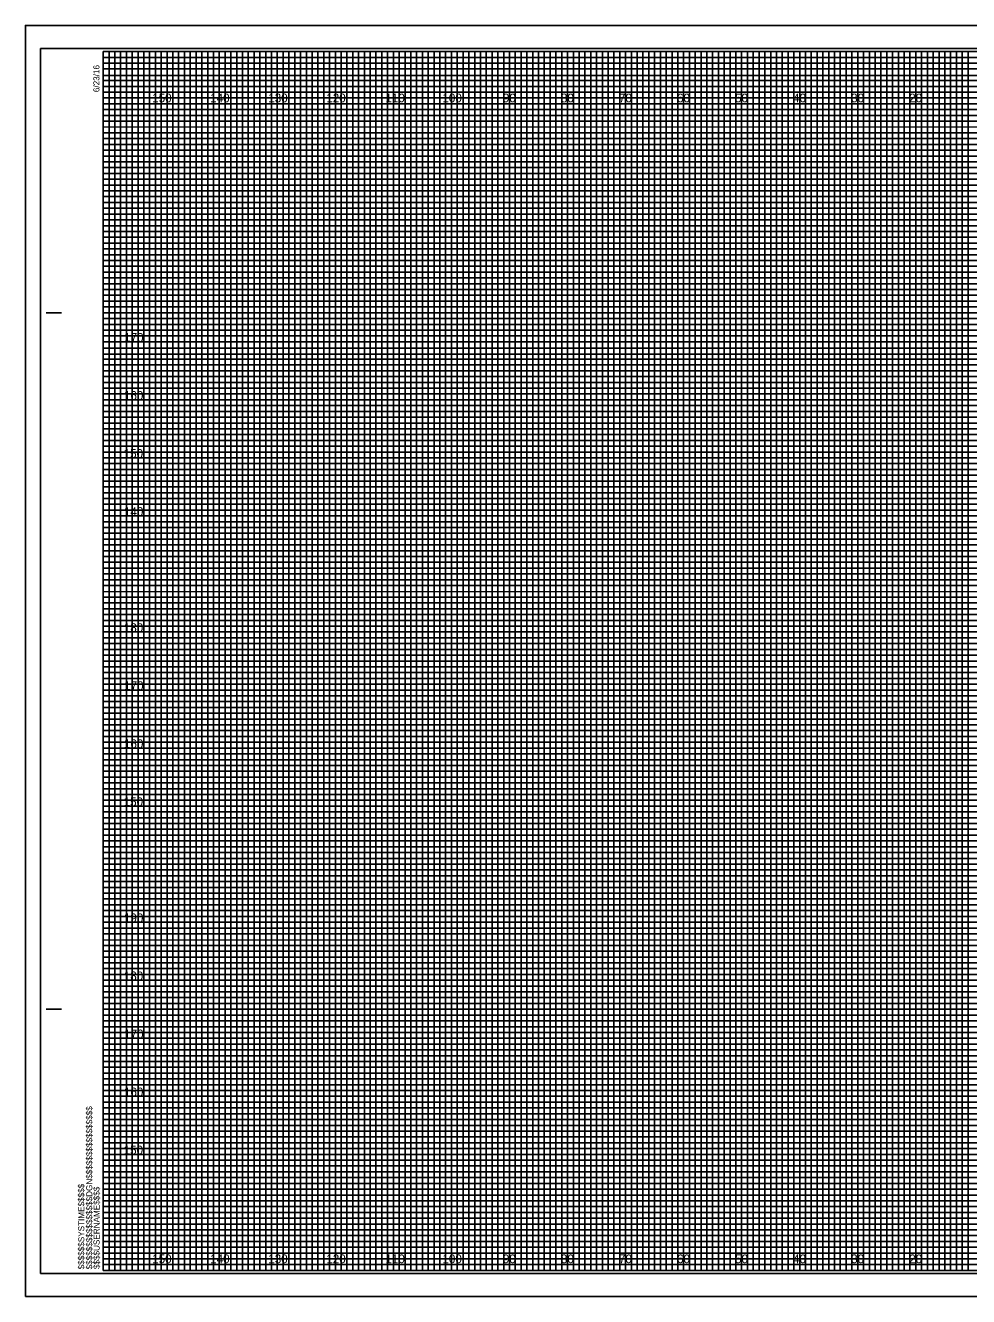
# Model space of a CAD drawing. Extents: x -13 to 323, y -5 to 4834.
# Drawn here: x -13.4 to 149.1, y 1095.5 to 1314.5 of the extents above; entities that cross this region are included whole.
import ezdxf

# ---------------------------------------------------------------- set-up
doc = ezdxf.new("R2010")
doc.units = 0
for name, color, linetype in [('Exist Cross Section Cell', 7, 'Continuous'), ('Exist XS Center Line Elevation Label', 7, 'Continuous'), ('Exist XS Ground Line', 7, 'Continuous'), ('Prop CMT Pvmt Course 1', 7, 'Continuous'), ('Prop CMT Pvmt Course 2', 7, 'Continuous'), ('Prop CMT Pvmt Course 3', 7, 'Continuous'), ('Prop CMT Pvmt Surface Shoulder', 7, 'Continuous'), ('Prop CMT Shld Paved Course 1', 7, 'Continuous'), ('Prop CMT Shld Paved Course 2', 7, 'Continuous'), ('Prop CMT Shld Paved Course 3', 7, 'Continuous'), ('Prop CMT Slope Grass', 7, 'Continuous')]:
    doc.layers.add(name, color=color, linetype=linetype)

msp = doc.modelspace()

# ---------------------------------------------------------------- linework, layer by layer
at = {"layer": 'Exist XS Center Line Elevation Label'}
for points in [[(0, 1310), (5, 1310), (5, 1100), (15, 1100), (15, 1310), (25, 1310), (25, 1100), (35, 1100), (35, 1310), (45, 1310), (45, 1100), (55, 1100), (55, 1310), (65, 1310), (65, 1100), (75, 1100), (75, 1310), (85, 1310), (85, 1100), (95, 1100), (95, 1310), (105, 1310), (105, 1100), (115, 1100), (115, 1310), (125, 1310), (125, 1100), (135, 1100), (135, 1310), (145, 1310), (145, 1100), (155, 1100)], [(0, 1305), (275, 1305)], [(0, 1285), (320, 1285), (320, 1295), (0, 1295)], [(0, 1265), (320, 1265), (320, 1275), (0, 1275)], [(0, 1245), (320, 1245), (320, 1255), (0, 1255)], [(0, 1225), (320, 1225), (320, 1235), (0, 1235)], [(0, 1205), (320, 1205), (320, 1215), (0, 1215)], [(0, 1185), (320, 1185), (320, 1195), (0, 1195)], [(0, 1165), (320, 1165), (320, 1175), (0, 1175)], [(0, 1145), (320, 1145), (320, 1155), (0, 1155)], [(0, 1125), (320, 1125), (320, 1135), (0, 1135)], [(0, 1105), (320, 1105), (320, 1115), (0, 1115)]]:
    msp.add_lwpolyline(points, dxfattribs=at)
at = {"layer": 'Exist XS Ground Line'}
for p, q in [((10, 1310), (0, 1310)), ((10, 1100), (10, 1310)), ((30, 1310), (20, 1310)), ((20, 1310), (20, 1100)), ((30, 1100), (30, 1310)), ((50, 1310), (40, 1310)), ((40, 1310), (40, 1100)), ((50, 1100), (50, 1310)), ((70, 1310), (60, 1310)), ((60, 1310), (60, 1100)), ((70, 1100), (70, 1310)), ((90, 1310), (80, 1310)), ((80, 1310), (80, 1100)), ((90, 1100), (90, 1310)), ((110, 1310), (100, 1310)), ((100, 1310), (100, 1100)), ((110, 1100), (110, 1310)), ((130, 1310), (120, 1310)), ((120, 1310), (120, 1100)), ((130, 1100), (130, 1310)), ((150, 1310), (140, 1310)), ((140, 1310), (140, 1100)), ((20, 1100), (10, 1100)), ((40, 1100), (30, 1100)), ((60, 1100), (50, 1100)), ((80, 1100), (70, 1100)), ((100, 1100), (90, 1100)), ((120, 1100), (110, 1100)), ((140, 1100), (130, 1100))]:
    msp.add_line(p, q, dxfattribs=at)
for points in [[(0, 1300), (320, 1300), (320, 1290), (0, 1290)], [(0, 1280), (320, 1280), (320, 1270), (0, 1270)], [(0, 1260), (320, 1260), (320, 1250), (0, 1250)], [(0, 1240), (320, 1240), (320, 1230), (0, 1230)], [(0, 1220), (320, 1220), (320, 1210), (0, 1210)], [(0, 1200), (320, 1200), (320, 1190), (0, 1190)], [(0, 1180), (320, 1180), (320, 1170), (0, 1170)], [(0, 1160), (320, 1160), (320, 1150), (0, 1150)], [(0, 1140), (320, 1140), (320, 1130), (0, 1130)], [(0, 1120), (320, 1120), (320, 1110), (0, 1110)]]:
    msp.add_lwpolyline(points, dxfattribs=at)
at = {"layer": 'Prop CMT Pvmt Course 1'}
for points in [[(0, 1100), (1, 1100), (1, 1310), (2, 1310), (2, 1100)], [(2, 1100), (3, 1100), (3, 1310), (4, 1310), (4, 1100)], [(5, 1100), (6, 1100), (6, 1310), (7, 1310), (7, 1100)], [(7, 1100), (8, 1100), (8, 1310), (9, 1310), (9, 1100)], [(10, 1100), (11, 1100), (11, 1310), (12, 1310), (12, 1100)], [(12, 1100), (13, 1100), (13, 1310), (14, 1310), (14, 1100)], [(15, 1100), (16, 1100), (16, 1310), (17, 1310), (17, 1100)], [(17, 1100), (18, 1100), (18, 1310), (19, 1310), (19, 1100)], [(20, 1100), (21, 1100), (21, 1310), (22, 1310), (22, 1100)], [(22, 1100), (23, 1100), (23, 1310), (24, 1310), (24, 1100)], [(25, 1100), (26, 1100), (26, 1310), (27, 1310), (27, 1100)], [(27, 1100), (28, 1100), (28, 1310), (29, 1310), (29, 1100)], [(30, 1100), (31, 1100), (31, 1310), (32, 1310), (32, 1100)], [(32, 1100), (33, 1100), (33, 1310), (34, 1310), (34, 1100)], [(35, 1100), (36, 1100), (36, 1310), (37, 1310), (37, 1100)], [(37, 1100), (38, 1100), (38, 1310), (39, 1310), (39, 1100)], [(40, 1100), (41, 1100), (41, 1310), (42, 1310), (42, 1100)], [(42, 1100), (43, 1100), (43, 1310), (44, 1310), (44, 1100)], [(45, 1100), (46, 1100), (46, 1310), (47, 1310), (47, 1100)], [(47, 1100), (48, 1100), (48, 1310), (49, 1310), (49, 1100)], [(50, 1100), (51, 1100), (51, 1310), (52, 1310), (52, 1100)], [(52, 1100), (53, 1100), (53, 1310), (54, 1310), (54, 1100)], [(55, 1100), (56, 1100), (56, 1310), (57, 1310), (57, 1100)], [(57, 1100), (58, 1100), (58, 1310), (59, 1310), (59, 1100)], [(60, 1100), (61, 1100), (61, 1310), (62, 1310), (62, 1100)], [(62, 1100), (63, 1100), (63, 1310), (64, 1310), (64, 1100)], [(65, 1100), (66, 1100), (66, 1310), (67, 1310), (67, 1100)], [(67, 1100), (68, 1100), (68, 1310), (69, 1310), (69, 1100)], [(70, 1100), (71, 1100), (71, 1310), (72, 1310), (72, 1100)], [(72, 1100), (73, 1100), (73, 1310), (74, 1310), (74, 1100)], [(75, 1100), (76, 1100), (76, 1310), (77, 1310), (77, 1100)], [(77, 1100), (78, 1100), (78, 1310), (79, 1310), (79, 1100)], [(80, 1100), (81, 1100), (81, 1310), (82, 1310), (82, 1100)], [(82, 1100), (83, 1100), (83, 1310), (84, 1310), (84, 1100)], [(85, 1100), (86, 1100), (86, 1310), (87, 1310), (87, 1100)], [(87, 1100), (88, 1100), (88, 1310), (89, 1310), (89, 1100)], [(90, 1100), (91, 1100), (91, 1310), (92, 1310), (92, 1100)], [(92, 1100), (93, 1100), (93, 1310), (94, 1310), (94, 1100)], [(95, 1100), (96, 1100), (96, 1310), (97, 1310), (97, 1100)], [(97, 1100), (98, 1100), (98, 1310), (99, 1310), (99, 1100)], [(100, 1100), (101, 1100), (101, 1310), (102, 1310), (102, 1100)], [(102, 1100), (103, 1100), (103, 1310), (104, 1310), (104, 1100)], [(105, 1100), (106, 1100), (106, 1310), (107, 1310), (107, 1100)], [(107, 1100), (108, 1100), (108, 1310), (109, 1310), (109, 1100)], [(110, 1100), (111, 1100), (111, 1310), (112, 1310), (112, 1100)], [(112, 1100), (113, 1100), (113, 1310), (114, 1310), (114, 1100)], [(115, 1100), (116, 1100), (116, 1310), (117, 1310), (117, 1100)], [(117, 1100), (118, 1100), (118, 1310), (119, 1310), (119, 1100)], [(120, 1100), (121, 1100), (121, 1310), (122, 1310), (122, 1100)], [(122, 1100), (123, 1100), (123, 1310), (124, 1310), (124, 1100)], [(125, 1100), (126, 1100), (126, 1310), (127, 1310), (127, 1100)], [(127, 1100), (128, 1100), (128, 1310), (129, 1310), (129, 1100)], [(130, 1100), (131, 1100), (131, 1310), (132, 1310), (132, 1100)], [(132, 1100), (133, 1100), (133, 1310), (134, 1310), (134, 1100)], [(135, 1100), (136, 1100), (136, 1310), (137, 1310), (137, 1100)], [(137, 1100), (138, 1100), (138, 1310), (139, 1310), (139, 1100)], [(140, 1100), (141, 1100), (141, 1310), (142, 1310), (142, 1100)], [(142, 1100), (143, 1100), (143, 1310), (144, 1310), (144, 1100)], [(145, 1100), (146, 1100), (146, 1310), (147, 1310), (147, 1100)], [(147, 1100), (148, 1100), (148, 1310), (149, 1310), (149, 1100)]]:
    msp.add_lwpolyline(points, dxfattribs=at)
at = {"layer": 'Prop CMT Pvmt Course 2'}
for p, q in [((323.3, 1314.5), (-13.4, 1314.5)), ((-13.4, 1314.5), (-13.4, 1095.5)), ((-13.4, 1095.5), (323.3, 1095.5))]:
    msp.add_line(p, q, dxfattribs=at)
at = {"layer": 'Prop CMT Pvmt Surface Shoulder'}
for p, q in [((-9.8, 1265), (-7.3, 1265)), ((-9.7, 1265), (-7.2, 1265)), ((-9.8, 1145), (-7.3, 1145)), ((-9.7, 1145), (-7.2, 1145)), ((0, 1100), (0, 1100)), ((0, 1100), (0, 1100)), ((0, 1100), (0, 1100)), ((0, 1100), (0, 1100)), ((0, 1100), (0, 1100)), ((0, 1100), (0, 1100)), ((0, 1100), (0, 1100))]:
    msp.add_line(p, q, dxfattribs=at)
msp.add_lwpolyline([(320, 1310), (0, 1310), (0, 1100), (320, 1100)], close=True, dxfattribs=at)
at = {"layer": 'Prop CMT Shld Paved Course 1'}
msp.add_lwpolyline([(-13.4, 1095.5), (323.3, 1095.5), (323.3, 1314.5), (-13.4, 1314.5)], close=True, dxfattribs=at)
at = {"layer": 'Prop CMT Shld Paved Course 2'}
msp.add_lwpolyline([(-10.8, 1099.5), (322.4, 1099.5), (322.4, 1310.5), (-10.8, 1310.5)], close=True, dxfattribs=at)
at = {"layer": 'Prop CMT Shld Paved Course 3'}
for p, q in [((10, 1100), (10, 1310)), ((20, 1100), (20, 1310)), ((30, 1100), (30, 1310)), ((40, 1100), (40, 1310)), ((50, 1100), (50, 1310)), ((60, 1100), (60, 1310)), ((70, 1100), (70, 1310)), ((80, 1100), (80, 1310)), ((90, 1100), (90, 1310)), ((100, 1100), (100, 1310)), ((110, 1100), (110, 1310)), ((120, 1100), (120, 1310)), ((130, 1100), (130, 1310)), ((140, 1100), (140, 1310)), ((0, 1300), (320, 1300)), ((0, 1290), (320, 1290)), ((0, 1280), (320, 1280)), ((0, 1270), (320, 1270)), ((0, 1260), (320, 1260)), ((0, 1250), (320, 1250)), ((0, 1240), (320, 1240)), ((0, 1230), (320, 1230)), ((0, 1220), (320, 1220)), ((0, 1210), (320, 1210)), ((0, 1200), (320, 1200)), ((0, 1190), (320, 1190)), ((0, 1180), (320, 1180)), ((0, 1170), (320, 1170)), ((0, 1160), (320, 1160)), ((0, 1150), (320, 1150)), ((0, 1140), (320, 1140)), ((0, 1130), (320, 1130)), ((0, 1120), (320, 1120)), ((0, 1110), (320, 1110))]:
    msp.add_line(p, q, dxfattribs=at)
at = {"layer": 'Prop CMT Slope Grass'}
for p, q in [((0, 1309), (260, 1309)), ((260, 1307.98), (0, 1307.98)), ((0, 1307.98), (0, 1307)), ((0, 1307), (260, 1307)), ((260, 1305.89), (0, 1305.89)), ((0, 1305.89), (0, 1304)), ((0, 1304), (320, 1304))]:
    msp.add_line(p, q, dxfattribs=at)
for points in [[(0, 1303), (270, 1303), (320, 1303), (320, 1302), (0, 1302)], [(0, 1301), (320, 1301), (320, 1299), (0, 1299)], [(0, 1298), (320, 1298), (320, 1297), (0, 1296.98)], [(0, 1296), (320, 1296), (320, 1294), (0, 1294)], [(0, 1293), (320, 1293), (320, 1292), (0, 1292)], [(0, 1291), (320, 1291), (320, 1289), (0, 1289)], [(0, 1288), (320, 1288), (320, 1287), (0, 1287)], [(0, 1286), (320, 1286), (320, 1284), (0, 1284)], [(0, 1283), (320, 1283), (320, 1282), (0, 1282)], [(0, 1281), (320, 1281), (320, 1279), (0, 1279)], [(0, 1278), (320, 1278), (320, 1277), (0, 1277)], [(0, 1276), (320, 1276), (320, 1273.95), (320, 1273), (320, 1272), (0, 1272)], [(0, 1274), (320, 1274), (320, 1273), (0, 1273)], [(0, 1271), (320, 1271), (320, 1269), (0, 1269.03)], [(0, 1269.03), (320, 1269), (320, 1268), (0, 1268)], [(0, 1267), (320, 1267), (320, 1266), (0, 1266)], [(0, 1264), (320, 1264), (320, 1263), (0, 1263)], [(0, 1262), (320, 1262), (320, 1261), (0, 1261)], [(-0.07, 1258.89), (320, 1258.89), (320, 1257.88), (-0.07, 1257.88)], [(0, 1257), (320, 1257), (320, 1256), (0, 1256)], [(0, 1254), (320, 1254), (320, 1253), (0, 1253)], [(0, 1252), (320, 1252), (320, 1251), (0, 1251)], [(0, 1249), (320, 1249), (320, 1248), (0, 1248)], [(0, 1247), (320, 1247), (320, 1246), (0, 1246)], [(0, 1244), (320, 1244), (320, 1243), (0, 1243)], [(0, 1242), (320, 1242), (320, 1241), (0, 1241)], [(0, 1239), (320, 1239), (319.99, 1237.98), (0, 1238)], [(0, 1237), (320, 1237), (320, 1236), (0, 1236)], [(0, 1234), (320, 1234), (320, 1233), (0, 1233)], [(0, 1232), (320, 1232), (320, 1231), (0, 1231)], [(0, 1229), (320, 1229), (320, 1228), (0, 1228)], [(0, 1227), (320, 1227), (320, 1226), (0, 1226)], [(0, 1224), (320, 1224), (320, 1223), (0, 1223)], [(0, 1222), (320, 1222), (320, 1221), (0, 1221)], [(0, 1219), (320, 1219), (320, 1218), (0, 1218)], [(0, 1216.99), (320.07, 1216.91), (320, 1216), (0, 1216)], [(0, 1214), (320, 1214), (320, 1213), (0, 1213)], [(0, 1212), (320, 1212), (320, 1211), (0, 1211)], [(0, 1209), (320, 1209), (320, 1208), (0, 1208)], [(0, 1207), (320, 1207), (320, 1206), (0, 1206)], [(0, 1204), (320, 1204), (320, 1203), (0, 1203)], [(0, 1202), (320, 1202), (320, 1201), (0, 1201)], [(0, 1199), (320, 1199), (320, 1198), (0, 1198)], [(0, 1197), (320, 1197), (320, 1196), (0, 1196)], [(0, 1194), (320, 1194), (320, 1193), (0, 1193)], [(0, 1192), (320, 1192), (320, 1191), (0, 1191)], [(0, 1189), (320, 1189), (320, 1188), (0, 1188)], [(0, 1187), (320, 1187), (320, 1186), (0, 1186)], [(0, 1184), (320, 1184), (320, 1183), (0, 1183)], [(0, 1182), (320, 1182), (320, 1181), (0, 1181)], [(0, 1179), (320, 1179), (319.99, 1177.98), (0, 1178)], [(0, 1177), (320, 1177), (320, 1176), (0, 1176)], [(0, 1174), (320, 1174), (320, 1173), (0, 1173)], [(0, 1172), (320, 1172), (320, 1171), (0, 1171)], [(0, 1169), (320, 1169), (320, 1168), (0, 1168)], [(0, 1167), (320, 1167), (320, 1166), (0, 1166)], [(0, 1164), (320, 1164), (320, 1163), (0, 1163)], [(0, 1162), (320, 1162), (320, 1161), (0, 1161)], [(0, 1159), (320, 1159), (320, 1158), (0, 1158)], [(0, 1156.99), (320.07, 1156.91), (320, 1156), (0, 1156)], [(0, 1154), (320, 1154), (320, 1153), (0, 1153)], [(0, 1152), (320, 1152), (320, 1151), (0, 1151)], [(0, 1149), (320, 1149), (320, 1148), (0, 1148)], [(0, 1147), (320, 1147), (320, 1146), (0, 1146)], [(0, 1144), (320, 1144), (320, 1143), (0, 1143)], [(0, 1142), (320, 1142), (320, 1141), (0, 1141)], [(0, 1139), (320, 1139), (320, 1138), (0, 1138)], [(0, 1137), (320, 1137), (320, 1136), (0, 1136)], [(0, 1134), (320, 1134), (320, 1133), (0, 1133)], [(0, 1132), (320, 1132), (320, 1131), (0, 1131)], [(0, 1129), (320, 1129), (320, 1128), (0, 1128)], [(0, 1127), (320, 1127), (320, 1126), (0, 1126)], [(0, 1124), (320, 1124), (320, 1123), (0, 1123)], [(0, 1122), (320, 1122), (320, 1121), (0, 1121)], [(0, 1119), (320, 1119), (320, 1118), (0, 1118)], [(0, 1117), (320, 1117), (320, 1116), (0, 1116)], [(0, 1114), (320, 1114), (320, 1113), (0, 1113)], [(0, 1112), (320, 1112), (320, 1111), (0, 1111)], [(0, 1109), (320, 1109), (320, 1108), (0, 1108)], [(0, 1107), (320, 1107), (320, 1106), (0, 1106)], [(0, 1104), (320, 1104), (320, 1103), (0, 1103)], [(0, 1102), (320, 1102), (320, 1101), (0, 1101)]]:
    msp.add_lwpolyline(points, dxfattribs=at)

# ---------------------------------------------------------------- texts
at = {"layer": 'Exist Cross Section Cell'}
for s, p in [('150', (8.44, 1301.25)), ('140', (18.44, 1301.25)), ('130', (28.44, 1301.25)), ('120', (38.44, 1301.25)), ('110', (48.62, 1301.25)), ('100', (58.44, 1301.25)), ('90', (68.86, 1301.25)), ('80', (78.86, 1301.25)), ('70', (88.86, 1301.25)), ('60', (98.86, 1301.25)), ('50', (108.86, 1301.25)), ('40', (118.86, 1301.25)), ('30', (128.86, 1301.25)), ('20', (138.86, 1301.25)), ('150', (8.44, 1101.25)), ('140', (18.44, 1101.25)), ('130', (28.44, 1101.25)), ('120', (38.44, 1101.25)), ('110', (48.62, 1101.25)), ('100', (58.44, 1101.25)), ('90', (68.86, 1101.25)), ('80', (78.86, 1101.25)), ('70', (88.86, 1101.25)), ('60', (98.86, 1101.25)), ('50', (108.86, 1101.25)), ('40', (118.86, 1101.25)), ('30', (128.86, 1101.25)), ('20', (138.86, 1101.25))]:
    msp.add_text(s, height=1.5, dxfattribs=at).set_placement(p)
at = {"layer": 'Prop CMT Pvmt Course 3'}
for s, p in [('170', (3.61, 1260)), ('160', (3.57, 1250)), ('150', (3.52, 1240)), ('140', (3.57, 1230)), ('180', (3.55, 1210)), ('170', (3.61, 1200)), ('160', (3.57, 1190)), ('150', (3.52, 1180)), ('190', (3.57, 1160)), ('180', (3.55, 1150)), ('170', (3.61, 1140)), ('160', (3.57, 1130)), ('150', (3.52, 1120))]:
    msp.add_text(s, height=1.5, dxfattribs=at).set_placement(p)
at = {"layer": 'Prop CMT Pvmt Surface Shoulder'}
for s, p in [('6/23/16', (-0.65, 1303)), ('$$$$$$$$$$$$$$$$DGN$$$$$$$$$$$$$$$$', (-1.88, 1100.18)), ('$$$$$$SYSTIME$$$$$', (-3.26, 1100.18)), ('$$$$USERNAME$$$$', (-0.62, 1100.23))]:
    msp.add_text(s, height=1.05, rotation=90, dxfattribs=at).set_placement(p)

doc.saveas('drawing.dxf')
